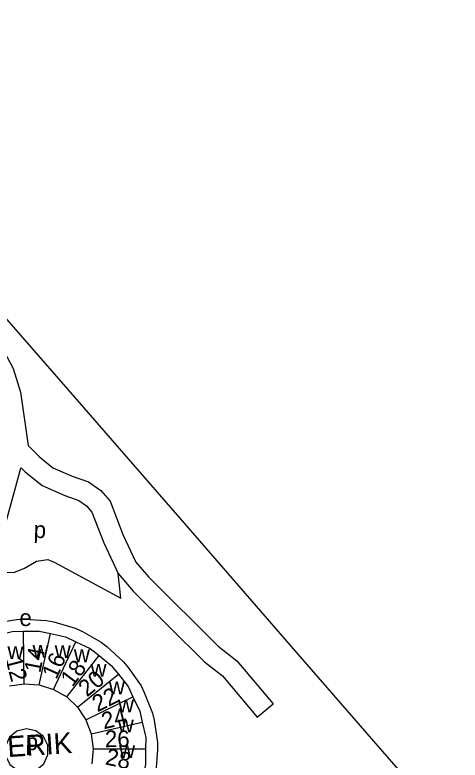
# Model space of a CAD drawing. Extents: x 155854 to 157362, y 383621 to 384685.
# Drawn here: x 157047.7 to 157154.8, y 384097.6 to 384276.9 of the extents above; entities that cross this region are included whole.
import ezdxf

# ---------------------------------------------------------------- set-up
doc = ezdxf.new("R2010")
doc.units = 0
for name, color, linetype in [('BLT_Basislijn', 7, 'Continuous'), ('BLT_Bebouwing', 7, 'Continuous'), ('BLT_Centroide', 7, 'Continuous'), ('BLT_Huisnummer', 7, 'Continuous'), ('BLT_Huisnummer_ tussenligend', 7, 'Continuous'), ('BLT_Onderverdeling_panden', 7, 'Continuous'), ('BLT_Straatnaam', 7, 'Continuous')]:
    doc.layers.add(name, color=color, linetype=linetype)

msp = doc.modelspace()

# ---------------------------------------------------------------- linework, layer by layer
at = {"layer": 'BLT_Basislijn'}
for p, q in [((157000.12, 384256.08), (157060.4, 384186.8)), ((157060.4, 384186.8), (157088.87, 384154.07)), ((157088.87, 384154.07), (157114.18, 384124.98))]:
    msp.add_line(p, q, dxfattribs=at)
for points in [[(156931.15, 384308.44), (156935.05, 384303.64), (156938.05, 384298.8), (156945.7, 384290.76), (156959.68, 384277.91), (156975.88, 384266.29), (156983.29, 384260.25), (156990.7, 384253.38), (157026.7, 384213.15), (157030.78, 384209.21), (157035.83, 384205.87), (157040, 384202.49), (157044.37, 384197.32), (157047.31, 384191.85), (157049.01, 384186.14), (157050.93, 384173.32)], [(157050.93, 384173.32), (157053.52, 384170.72), (157056.86, 384167.99), (157061.5, 384165.96), (157065.43, 384164.63), (157068.36, 384162.52), (157070.58, 384159.9), (157073.68, 384151.9), (157076.81, 384145.25), (157079.81, 384141.72), (157096.63, 384125.06), (157101.1, 384121.53), (157109.79, 384111.18)], [(157049.19, 384167.98), (157049.07, 384167.8), (157045.29, 384154.04), (157042.49, 384150.85), (157032.95, 384143.86), (157032.64, 384143.02), (157032.67, 384142.15), (157034.24, 384138.8)], [(157049.19, 384167.98), (157050.16, 384167.01), (157054.22, 384163.69), (157059.69, 384161.3), (157063.11, 384160.13), (157064.94, 384158.82), (157066.22, 384157.31), (157069.08, 384149.93), (157072.57, 384142.52)], [(157034.24, 384138.8), (157038.65, 384141.19), (157042.69, 384142.82), (157047.48, 384142.77), (157050.02, 384143.84), (157052.89, 384145.51), (157055.6, 384145.94), (157057.17, 384145.3), (157073.18, 384136.62), (157072.57, 384142.52)], [(157072.57, 384142.52), (157076.13, 384138.32), (157093.31, 384121.31), (157097.6, 384117.92), (157105.96, 384107.96), (157109.79, 384111.18)], [(157043.03, 384130.64), (157048.13, 384131.48), (157049.9, 384131.54), (157055.3, 384131.25), (157057.03, 384130.89), (157062.17, 384129.36), (157063.95, 384128.55), (157068.47, 384126.01), (157069.88, 384124.93), (157073.85, 384121.32), (157074.97, 384119.96), (157078.07, 384115.49), (157078.78, 384113.91), (157080.76, 384108.94), (157081.17, 384107.24), (157081.98, 384101.91), (157082, 384100.14), (157081.59, 384094.78)], [(157114.18, 384124.98), (157222.9, 383999.98)]]:
    msp.add_lwpolyline(points, dxfattribs=at)
msp.add_lwpolyline([(157050.45, 384105.18), (157048.19, 384104.63), (157046.39, 384103.15), (157045.41, 384101.03), (157045.45, 384098.71), (157046.49, 384096.62), (157048.34, 384095.2), (157050.61, 384094.72), (157052.88, 384095.27), (157054.68, 384096.75), (157055.65, 384098.87), (157055.62, 384101.2), (157054.57, 384103.28), (157052.73, 384104.7)], close=True, dxfattribs=at)
at = {"layer": 'BLT_Bebouwing'}
for p, q in [((157046.38, 384115.49), (157049.95, 384116.01)), ((157049.95, 384116.01), (157053.56, 384115.74)), ((157053.56, 384115.74), (157057.02, 384114.65)), ((157057.02, 384114.65), (157060.16, 384112.83)), ((157060.16, 384112.83), (157062.77, 384110.35)), ((157062.77, 384110.35), (157064.78, 384107.35)), ((157064.78, 384107.35), (157066.05, 384103.96)), ((157066.05, 384103.96), (157066.55, 384100.37)), ((157066.55, 384100.37), (157066.19, 384096.77))]:
    msp.add_line(p, q, dxfattribs=at)
for points in [[(157043.55, 384127.73), (157047.01, 384128.62), (157049.76, 384128.67)], [(157049.76, 384128.67), (157053.51, 384128.69), (157056.24, 384128.12)], [(157056.24, 384128.12), (157059.9, 384127.28), (157062.38, 384126.13)], [(157062.38, 384126.13), (157065.78, 384124.49), (157067.96, 384122.79)], [(157067.96, 384122.79), (157070.88, 384120.43), (157072.62, 384118.29)], [(157072.62, 384118.29), (157074.95, 384115.35), (157076.1, 384112.84)], [(157076.1, 384112.84), (157077.74, 384109.45), (157078.33, 384106.78)], [(157078.33, 384106.78), (157079.17, 384103.11), (157079.14, 384100.33)], [(157079.14, 384100.33), (157079.1, 384096.55), (157078.48, 384093.89)]]:
    msp.add_lwpolyline(points, dxfattribs=at)
at = {"layer": 'BLT_Onderverdeling_panden'}
for p, q in [((157049.95, 384116.01), (157049.76, 384128.67)), ((157053.56, 384115.74), (157056.24, 384128.12)), ((157057.02, 384114.65), (157062.38, 384126.13)), ((157060.16, 384112.83), (157067.96, 384122.79)), ((157062.77, 384110.35), (157072.62, 384118.29)), ((157064.78, 384107.35), (157076.1, 384112.84)), ((157066.05, 384103.96), (157078.33, 384106.78)), ((157066.55, 384100.37), (157079.14, 384100.33))]:
    msp.add_line(p, q, dxfattribs=at)

# ---------------------------------------------------------------- texts
at = {"layer": 'BLT_Centroide'}
for p in [(157052.17, 384151.12), (157050.25, 384100.1)]:
    msp.add_text('p', height=4, rotation=358, dxfattribs=at).set_placement(p)
for s, p in [('e', (157048.79, 384129.9)), ('w', (157045.91, 384121.94)), ('w', (157051.94, 384122.28)), ('w', (157057.28, 384122.17)), ('w', (157061.88, 384121.2)), ('w', (157065.89, 384117.72)), ('w', (157070.29, 384113.44)), ('w', (157072.49, 384109.12)), ('w', (157072.44, 384104.31)), ('w', (157072.75, 384098.16))]:
    msp.add_text(s, height=4, dxfattribs=at).set_placement(p)
at = {"layer": 'BLT_Huisnummer'}
for s, rotation, p in [('14', 78.7239, (157053.79, 384118.45)), ('18', 52.7213, (157061.52, 384115.05)), ('22', 26.7199, (157067.57, 384109.1)), ('26', 0.7175, (157069.37, 384100.74))]:
    msp.add_text(s, height=4, rotation=rotation, dxfattribs=at).set_placement(p)
at = {"layer": 'BLT_Huisnummer_ tussenligend'}
for s, rotation, p in [('12', 284.7259, (157045.39, 384121.95)), ('16', 65.7239, (157057.67, 384116.86)), ('20', 39.7209, (157065.05, 384112.68)), ('24', 13.7183, (157069.08, 384105.03)), ('28', 347.7163, (157069.25, 384096.64))]:
    msp.add_text(s, height=4, rotation=rotation, dxfattribs=at).set_placement(p)
at = {"layer": 'BLT_Straatnaam'}
msp.add_text('BOSLEEUWERIK', height=5, rotation=3.6873, dxfattribs=at).set_placement((157008.21, 384095.92))

doc.saveas('drawing.dxf')
